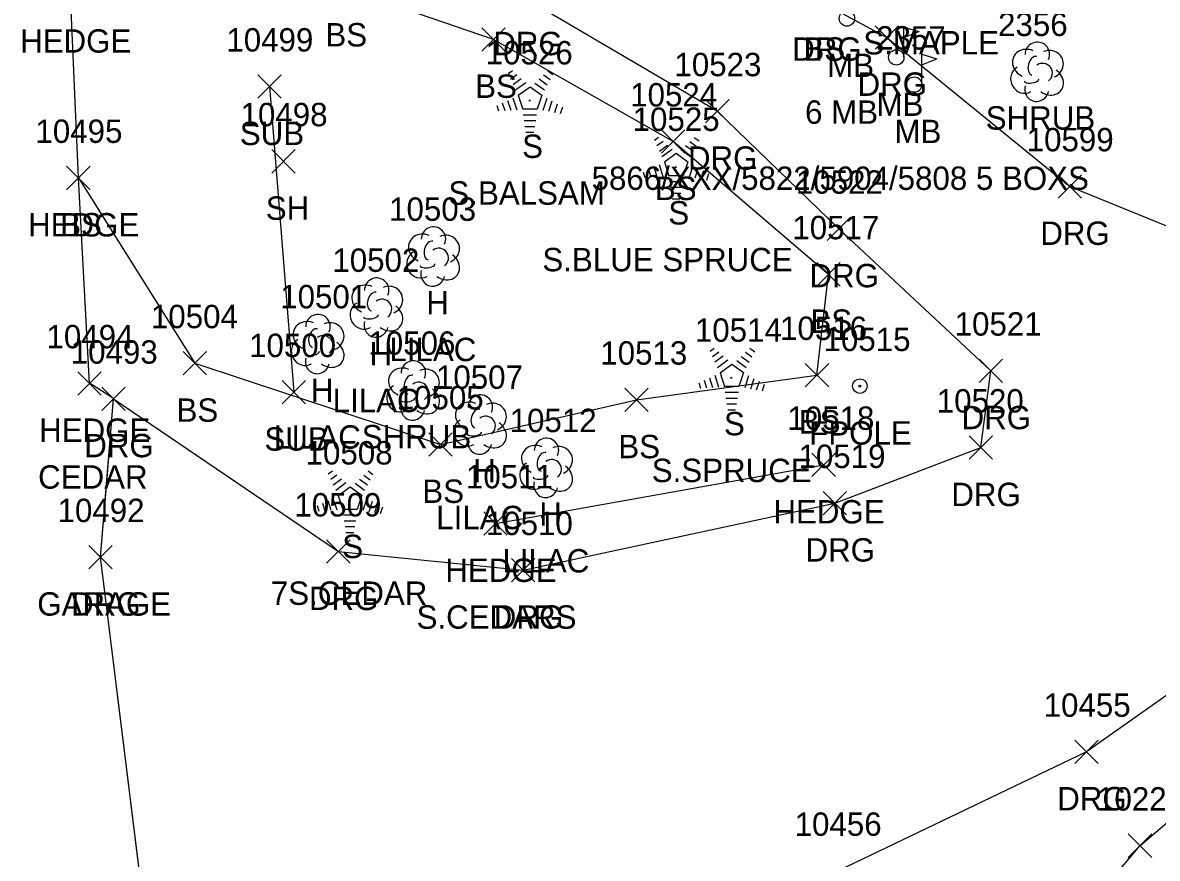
# Model space of a CAD drawing. Extents: x 1439173 to 1457902, y 641926 to 659889.
# Drawn here: x 1448003.1 to 1448100.1, y 647159.4 to 647230.9 of the extents above; entities that cross this region are included whole.
import ezdxf

# ---------------------------------------------------------------- set-up
doc = ezdxf.new("R2010")
doc.units = 0
for name, color, linetype in [('L_A', 7, 'Continuous'), ('L_C', 7, 'Continuous'), ('L_I', 7, 'Continuous'), ('L_TIC', 7, 'Continuous'), ('LAHR', 7, 'Continuous'), ('LBC', 7, 'Continuous'), ('LELB', 7, 'Continuous'), ('LFP', 7, 'Continuous'), ('LMB', 7, 'Continuous'), ('LSH', 7, 'Continuous'), ('LSOGP', 7, 'Continuous'), ('LTC', 7, 'Continuous'), ('LTD', 7, 'Continuous'), ('R_A', 7, 'Continuous'), ('R_I', 7, 'Continuous'), ('R_TIC', 7, 'Continuous'), ('RDG', 7, 'Continuous'), ('U_A', 7, 'Continuous'), ('U_I', 7, 'Continuous'), ('U_TIC', 7, 'Continuous'), ('UUU', 7, 'Continuous')]:
    doc.layers.add(name, color=color, linetype=linetype)

msp = doc.modelspace()

# ---------------------------------------------------------------- linework, layer by layer
at = {"layer": 'L_TIC'}
for points in [[(1448042.314, 647228.432), (1448044.314, 647230.432)], [(1448044.314, 647228.432), (1448042.314, 647230.432)], [(1448057.681, 647219.696), (1448059.681, 647221.696)], [(1448059.681, 647219.696), (1448057.681, 647221.696)], [(1448024.365, 647218.006), (1448026.365, 647220.006)], [(1448026.365, 647218.006), (1448024.365, 647220.006)], [(1448006.825, 647216.582), (1448008.825, 647218.582)], [(1448008.825, 647216.582), (1448006.825, 647218.582)], [(1448006.825, 647216.582), (1448008.825, 647218.582)], [(1448008.825, 647216.582), (1448006.825, 647218.582)], [(1448070.981, 647208.343), (1448072.981, 647210.343)], [(1448072.981, 647208.343), (1448070.981, 647210.343)], [(1448016.779, 647200.739), (1448018.779, 647202.739)], [(1448018.779, 647200.739), (1448016.779, 647202.739)], [(1448069.987, 647199.734), (1448071.987, 647201.734)], [(1448071.987, 647199.734), (1448069.987, 647201.734)], [(1448007.77, 647199.02), (1448009.77, 647201.02)], [(1448009.77, 647199.02), (1448007.77, 647201.02)], [(1448054.559, 647197.621), (1448056.559, 647199.621)], [(1448056.559, 647197.621), (1448054.559, 647199.621)], [(1448037.796, 647193.8), (1448039.796, 647195.8)], [(1448039.796, 647193.8), (1448037.796, 647195.8)], [(1448070.56, 647192.046), (1448072.56, 647194.046)], [(1448072.56, 647192.046), (1448070.56, 647194.046)], [(1448042.505, 647187.044), (1448044.505, 647189.044)], [(1448044.505, 647187.044), (1448042.505, 647189.044)], [(1448008.715, 647184.162), (1448010.715, 647186.162)], [(1448010.715, 647184.162), (1448008.715, 647186.162)], [(1448097.606, 647159.494), (1448099.606, 647161.494)], [(1448099.606, 647159.494), (1448097.606, 647161.494)]]:
    msp.add_lwpolyline(points, dxfattribs=at)
at = {"layer": 'LAHR'}
for points in [[(1448008.77, 647200.02), (1448007.825, 647217.582), (1448007.146, 647233.297)], [(1448043.505, 647188.044), (1448071.56, 647193.046)], [(1448080.435, 647069.069), (1448093.61, 647079.441), (1448095.055, 647091.51), (1448086.709, 647103.901), (1448078.141, 647117.067), (1448077.759, 647130.824), (1448085.363, 647144.088), (1448090.665, 647151.083), (1448098.606, 647160.494), (1448114.208, 647173.812)]]:
    msp.add_lwpolyline(points, dxfattribs=at)
at = {"layer": 'LBC'}
msp.add_lwpolyline([(1448014.179, 647149.261), (1448009.715, 647185.162)], dxfattribs=at)
at = {"layer": 'LELB'}
msp.add_lwpolyline([(1448007.825, 647217.582), (1448017.779, 647201.739), (1448038.796, 647194.8), (1448055.559, 647198.621), (1448070.987, 647200.734), (1448071.981, 647209.343), (1448058.681, 647220.696), (1448043.314, 647229.432), (1448030.507, 647233.829), (1448022.679, 647242.591)], dxfattribs=at)
at = {"layer": 'LFP'}
for radius in [0.625, 0.0833]:
    msp.add_circle((1448074.652, 647199.785), radius, dxfattribs=at)
at = {"layer": 'LMB'}
for p, q in [((1448078.418, 647230.491), (1448079.712, 647230.109)), ((1448078.424, 647227.899), (1448078.423, 647230.494)), ((1448078.423, 647229.592), (1448079.706, 647230.1)), ((1448077.768, 647227.891), (1448077.768, 647227.891)), ((1448079.954, 647228.163), (1448081.248, 647227.781)), ((1448079.96, 647225.571), (1448079.959, 647228.166)), ((1448079.959, 647227.264), (1448081.242, 647227.772)), ((1448079.304, 647225.563), (1448079.304, 647225.563))]:
    msp.add_line(p, q, dxfattribs=at)
for centre in [(1448073.55, 647231.217), (1448077.768, 647227.891), (1448079.304, 647225.563)]:
    msp.add_circle(centre, 0.656, dxfattribs=at)
at = {"layer": 'LSH'}
for p, q in [((1448089.785, 647226.719), (1448089.785, 647226.719)), ((1448089.785, 647226.719), (1448089.785, 647226.719)), ((1448036.43, 647199.464), (1448036.43, 647199.464)), ((1448036.43, 647199.464), (1448036.43, 647199.464))]:
    msp.add_line(p, q, dxfattribs=at)
for centre in [(1448089.831, 647228.153), (1448036.476, 647200.898)]:
    msp.add_arc(centre, 1.047, 335.52715, 180.95627, dxfattribs=at)
for centre, major_axis, ratio, start_param, end_param in [((1448088.993, 647227.385), (1.21, -0.512), 0.895232, 1.570796, 4.712389), ((1448089.576, 647227.177), (-0.208, -0.792), 0.645439, 3.141593, 6.283185), ((1448090.826, 647227.302), (-1.141, -0.483), 0.949671, 1.570796, 4.712389), ((1448088.702, 647226.01), (0.584, -1.042), 0.959034, 3.141593, 6.283185), ((1448090.285, 647226.552), (-0.5, 0.667), 0.989748, 3.141593, 6.283185), ((1448089.327, 647225.969), (-0.625, -0.083), 0.423636, 0, 3.141593), ((1448090.785, 647225.886), (-1.09, 0.792), 0.841452, 1.570796, 4.712389), ((1448089.785, 647225.219), (0.265, 1.061), 0.942809, 1.570796, 4.712389), ((1448035.638, 647200.131), (1.21, -0.512), 0.895232, 1.570796, 4.712389), ((1448036.221, 647199.923), (-0.208, -0.792), 0.645439, 3.141593, 6.283185), ((1448037.471, 647200.048), (-1.141, -0.483), 0.949671, 1.570796, 4.712389), ((1448035.347, 647198.756), (0.584, -1.042), 0.959034, 3.141593, 6.283185), ((1448036.93, 647199.298), (-0.5, 0.667), 0.989748, 3.141593, 6.283185), ((1448035.972, 647198.714), (-0.625, -0.083), 0.423636, 0, 3.141593), ((1448037.43, 647198.631), (-1.09, 0.792), 0.841452, 1.570796, 4.712389), ((1448036.43, 647197.964), (0.265, 1.061), 0.942809, 1.570796, 4.712389)]:
    msp.add_ellipse(centre, major_axis=major_axis, ratio=ratio, start_param=start_param, end_param=end_param, dxfattribs=at)
at = {"layer": 'LSOGP'}
msp.add_lwpolyline([(1448014.178, 647149.273), (1448009.714, 647185.174), (1448010.279, 647191.946), (1448010.844, 647198.718), (1448008.768, 647200.031), (1448007.825, 647217.593), (1448007.147, 647233.309), (1448010.527, 647240.895), (1448022.681, 647242.603), (1448028.133, 647243.372), (1448023.368, 647278.648), (1448017.454, 647321.225)], dxfattribs=at)
at = {"layer": 'LTC'}
for p, q in [((1448044.582, 647226.505), (1448044.936, 647226.763)), ((1448044.791, 647226.04), (1448045.321, 647226.424)), ((1448045.001, 647225.574), (1448045.705, 647226.085)), ((1448047.238, 647226.049), (1448047.917, 647225.555)), ((1448047.609, 647226.397), (1448048.158, 647225.998)), ((1448047.98, 647226.745), (1448048.399, 647226.441)), ((1448045.211, 647225.108), (1448046.089, 647225.746)), ((1448045.435, 647224.653), (1448046.447, 647225.388)), ((1448046.447, 647225.388), (1448047.444, 647224.663)), ((1448046.867, 647225.7), (1448047.676, 647225.112)), ((1448044.07, 647224.001), (1448044.281, 647223.349)), ((1448044.525, 647224.218), (1448044.796, 647223.382)), ((1448044.981, 647224.434), (1448045.311, 647223.415)), ((1448045.435, 647224.653), (1448045.822, 647223.46)), ((1448047.444, 647224.663), (1448047.053, 647223.46)), ((1448047.881, 647224.392), (1448047.543, 647223.352)), ((1448048.326, 647224.141), (1448048.038, 647223.257)), ((1448043.614, 647223.784), (1448043.766, 647223.316)), ((1448047.053, 647223.46), (1448045.822, 647223.46)), ((1448048.771, 647223.891), (1448048.533, 647223.162)), ((1448049.215, 647223.641), (1448049.028, 647223.067)), ((1448047.014, 647222.96), (1448045.87, 647222.96)), ((1448046.931, 647222.46), (1448045.942, 647222.46)), ((1448046.847, 647221.96), (1448046.015, 647221.96)), ((1448046.763, 647221.46), (1448046.088, 647221.46)), ((1448057.086, 647220.813), (1448057.441, 647221.07)), ((1448057.296, 647220.347), (1448057.825, 647220.732)), ((1448057.506, 647219.882), (1448058.209, 647220.393)), ((1448059.743, 647220.357), (1448060.422, 647219.863)), ((1448060.113, 647220.705), (1448060.663, 647220.306)), ((1448060.485, 647221.053), (1448060.904, 647220.749)), ((1448057.715, 647219.416), (1448058.593, 647220.054)), ((1448057.94, 647218.961), (1448058.951, 647219.695)), ((1448058.951, 647219.695), (1448059.948, 647218.97)), ((1448059.371, 647220.008), (1448060.181, 647219.419)), ((1448056.574, 647218.309), (1448056.786, 647217.657)), ((1448057.03, 647218.525), (1448057.301, 647217.69)), ((1448057.485, 647218.742), (1448057.816, 647217.722)), ((1448057.94, 647218.961), (1448058.327, 647217.767)), ((1448059.948, 647218.97), (1448059.557, 647217.767)), ((1448060.386, 647218.699), (1448060.048, 647217.66)), ((1448060.831, 647218.449), (1448060.543, 647217.564)), ((1448061.275, 647218.199), (1448061.038, 647217.469)), ((1448056.119, 647218.092), (1448056.271, 647217.624)), ((1448059.557, 647217.767), (1448058.327, 647217.767)), ((1448059.519, 647217.267), (1448058.374, 647217.267)), ((1448061.719, 647217.949), (1448061.533, 647217.374)), ((1448059.435, 647216.767), (1448058.447, 647216.767)), ((1448059.351, 647216.267), (1448058.52, 647216.267)), ((1448059.268, 647215.767), (1448058.593, 647215.767)), ((1448061.843, 647202.787), (1448062.197, 647203.044)), ((1448062.052, 647202.321), (1448062.581, 647202.705)), ((1448064.87, 647202.679), (1448065.419, 647202.279)), ((1448065.241, 647203.027), (1448065.66, 647202.722)), ((1448062.262, 647201.855), (1448062.965, 647202.367)), ((1448062.471, 647201.389), (1448063.35, 647202.027)), ((1448062.696, 647200.934), (1448063.708, 647201.669)), ((1448063.708, 647201.669), (1448064.705, 647200.944)), ((1448064.128, 647201.982), (1448064.937, 647201.393)), ((1448064.499, 647202.33), (1448065.178, 647201.837)), ((1448062.241, 647200.715), (1448062.572, 647199.696)), ((1448062.696, 647200.934), (1448063.083, 647199.741)), ((1448064.705, 647200.944), (1448064.313, 647199.741)), ((1448060.875, 647200.066), (1448061.027, 647199.598)), ((1448061.33, 647200.282), (1448061.542, 647199.631)), ((1448061.786, 647200.499), (1448062.057, 647199.664)), ((1448064.313, 647199.741), (1448063.083, 647199.741)), ((1448065.142, 647200.673), (1448064.804, 647199.634)), ((1448065.587, 647200.423), (1448065.299, 647199.538)), ((1448066.031, 647200.173), (1448065.794, 647199.443)), ((1448066.475, 647199.922), (1448066.289, 647199.348)), ((1448064.275, 647199.241), (1448063.13, 647199.241)), ((1448064.191, 647198.741), (1448063.203, 647198.741)), ((1448064.108, 647198.241), (1448063.276, 647198.241)), ((1448064.024, 647197.741), (1448063.349, 647197.741)), ((1448029.201, 647192.292), (1448029.556, 647192.55)), ((1448029.411, 647191.827), (1448029.94, 647192.211)), ((1448032.228, 647192.184), (1448032.778, 647191.785)), ((1448032.6, 647192.533), (1448033.019, 647192.228)), ((1448029.62, 647191.361), (1448030.324, 647191.872)), ((1448029.83, 647190.895), (1448030.708, 647191.533)), ((1448030.055, 647190.44), (1448031.066, 647191.175)), ((1448031.066, 647191.175), (1448032.063, 647190.45)), ((1448031.486, 647191.488), (1448032.296, 647190.899)), ((1448031.858, 647191.836), (1448032.537, 647191.342)), ((1448029.6, 647190.221), (1448029.931, 647189.202)), ((1448030.055, 647190.44), (1448030.442, 647189.247)), ((1448032.063, 647190.45), (1448031.672, 647189.247)), ((1448032.501, 647190.179), (1448032.163, 647189.139)), ((1448028.234, 647189.571), (1448028.386, 647189.104)), ((1448028.689, 647189.788), (1448028.901, 647189.136)), ((1448029.145, 647190.005), (1448029.416, 647189.169)), ((1448031.672, 647189.247), (1448030.442, 647189.247)), ((1448032.945, 647189.929), (1448032.658, 647189.044)), ((1448033.39, 647189.679), (1448033.153, 647188.949)), ((1448033.834, 647189.428), (1448033.648, 647188.854)), ((1448031.634, 647188.747), (1448030.489, 647188.747)), ((1448031.55, 647188.247), (1448030.562, 647188.247)), ((1448031.466, 647187.747), (1448030.635, 647187.747)), ((1448031.383, 647187.247), (1448030.708, 647187.247))]:
    msp.add_line(p, q, dxfattribs=at)
at = {"layer": 'LTD'}
for p, q in [((1448038.146, 647210.922), (1448038.146, 647210.922)), ((1448038.146, 647210.922), (1448038.146, 647210.922)), ((1448033.295, 647206.556), (1448033.295, 647206.556)), ((1448033.295, 647206.556), (1448033.295, 647206.556)), ((1448028.271, 647203.437), (1448028.271, 647203.437)), ((1448028.271, 647203.437), (1448028.271, 647203.437)), ((1448042.155, 647196.555), (1448042.155, 647196.555)), ((1448042.155, 647196.555), (1448042.155, 647196.555)), ((1448047.809, 647192.853), (1448047.809, 647192.853)), ((1448047.809, 647192.853), (1448047.809, 647192.853))]:
    msp.add_line(p, q, dxfattribs=at)
for centre in [(1448038.193, 647212.355), (1448033.342, 647207.99), (1448028.317, 647204.87), (1448042.202, 647197.989), (1448047.855, 647194.287)]:
    msp.add_arc(centre, 1.047, 335.52715, 180.95627, dxfattribs=at)
for centre, major_axis, ratio, start_param, end_param in [((1448037.354, 647211.588), (1.21, -0.512), 0.895232, 1.570796, 4.712389), ((1448039.188, 647211.505), (-1.141, -0.483), 0.949671, 1.570796, 4.712389), ((1448037.938, 647211.38), (-0.208, -0.792), 0.645439, 3.141593, 6.283185), ((1448038.646, 647210.755), (-0.5, 0.667), 0.989748, 3.141593, 6.283185), ((1448037.063, 647210.213), (0.584, -1.042), 0.959034, 3.141593, 6.283185), ((1448039.146, 647210.088), (-1.09, 0.792), 0.841452, 1.570796, 4.712389), ((1448038.146, 647209.422), (0.265, 1.061), 0.942809, 1.570796, 4.712389), ((1448037.688, 647210.171), (-0.625, -0.083), 0.423636, 0, 3.141593), ((1448032.503, 647207.222), (1.21, -0.512), 0.895232, 1.570796, 4.712389), ((1448034.336, 647207.139), (-1.141, -0.483), 0.949671, 1.570796, 4.712389), ((1448033.087, 647207.014), (-0.208, -0.792), 0.645439, 3.141593, 6.283185), ((1448032.212, 647205.847), (0.584, -1.042), 0.959034, 3.141593, 6.283185), ((1448033.795, 647206.389), (-0.5, 0.667), 0.989748, 3.141593, 6.283185), ((1448034.295, 647205.722), (-1.09, 0.792), 0.841452, 1.570796, 4.712389), ((1448032.837, 647205.806), (-0.625, -0.083), 0.423636, 0, 3.141593), ((1448027.479, 647204.103), (1.21, -0.512), 0.895232, 1.570796, 4.712389), ((1448028.062, 647203.895), (-0.208, -0.792), 0.645439, 3.141593, 6.283185), ((1448029.312, 647204.02), (-1.141, -0.483), 0.949671, 1.570796, 4.712389), ((1448033.295, 647205.056), (0.265, 1.061), 0.942809, 1.570796, 4.712389), ((1448027.187, 647202.728), (0.584, -1.042), 0.959034, 3.141593, 6.283185), ((1448028.771, 647203.27), (-0.5, 0.667), 0.989748, 3.141593, 6.283185), ((1448027.812, 647202.686), (-0.625, -0.083), 0.423636, 0, 3.141593), ((1448029.271, 647202.603), (-1.09, 0.792), 0.841452, 1.570796, 4.712389), ((1448028.271, 647201.937), (0.265, 1.061), 0.942809, 1.570796, 4.712389), ((1448041.363, 647197.222), (1.21, -0.512), 0.895232, 1.570796, 4.712389), ((1448041.947, 647197.014), (-0.208, -0.792), 0.645439, 3.141593, 6.283185), ((1448043.197, 647197.139), (-1.141, -0.483), 0.949671, 1.570796, 4.712389), ((1448041.072, 647195.847), (0.584, -1.042), 0.959034, 3.141593, 6.283185), ((1448042.655, 647196.389), (-0.5, 0.667), 0.989748, 3.141593, 6.283185), ((1448041.697, 647195.805), (-0.625, -0.083), 0.423636, 0, 3.141593), ((1448043.155, 647195.722), (-1.09, 0.792), 0.841452, 1.570796, 4.712389), ((1448042.155, 647195.055), (0.265, 1.061), 0.942809, 1.570796, 4.712389), ((1448047.017, 647193.52), (1.21, -0.512), 0.895232, 1.570796, 4.712389), ((1448047.6, 647193.311), (-0.208, -0.792), 0.645439, 3.141593, 6.283185), ((1448048.85, 647193.437), (-1.141, -0.483), 0.949671, 1.570796, 4.712389), ((1448046.725, 647192.145), (0.584, -1.042), 0.959034, 3.141593, 6.283185), ((1448048.309, 647192.686), (-0.5, 0.667), 0.989748, 3.141593, 6.283185), ((1448048.809, 647192.02), (-1.09, 0.792), 0.841452, 1.570796, 4.712389), ((1448047.35, 647192.103), (-0.625, -0.083), 0.423636, 0, 3.141593), ((1448047.809, 647191.353), (0.265, 1.061), 0.942809, 1.570796, 4.712389)]:
    msp.add_ellipse(centre, major_axis=major_axis, ratio=ratio, start_param=start_param, end_param=end_param, dxfattribs=at)
at = {"layer": 'R_TIC'}
for points in [[(1448075.967, 647228.606), (1448077.967, 647230.606)], [(1448077.967, 647228.606), (1448075.967, 647230.606)], [(1448061.464, 647222.285), (1448063.464, 647224.285)], [(1448063.464, 647222.285), (1448061.464, 647224.285)], [(1448091.597, 647215.862), (1448093.597, 647217.862)], [(1448093.597, 647215.862), (1448091.597, 647217.862)], [(1448071.853, 647212.238), (1448073.853, 647214.238)], [(1448073.853, 647212.238), (1448071.853, 647214.238)], [(1448084.863, 647200.104), (1448086.863, 647202.104)], [(1448086.863, 647200.104), (1448084.863, 647202.104)], [(1448009.842, 647197.705), (1448011.842, 647199.705)], [(1448011.842, 647197.705), (1448009.842, 647199.705)], [(1448083.986, 647193.529), (1448085.986, 647195.529)], [(1448085.986, 647193.529), (1448083.986, 647195.529)], [(1448071.517, 647188.786), (1448073.517, 647190.786)], [(1448073.517, 647188.786), (1448071.517, 647190.786)], [(1448008.715, 647184.162), (1448010.715, 647186.162)], [(1448010.715, 647184.162), (1448008.715, 647186.162)], [(1448029.057, 647184.639), (1448031.057, 647186.639)], [(1448031.057, 647184.639), (1448029.057, 647186.639)], [(1448044.859, 647183.051), (1448046.859, 647185.051)], [(1448046.859, 647183.051), (1448044.859, 647185.051)], [(1448093.039, 647167.513), (1448095.039, 647169.513)], [(1448095.039, 647167.513), (1448093.039, 647169.513)]]:
    msp.add_lwpolyline(points, dxfattribs=at)
at = {"layer": 'RDG'}
for points in [[(1448009.715, 647185.162), (1448010.842, 647198.705), (1448030.057, 647185.639), (1448045.859, 647184.051), (1448072.517, 647189.786), (1448084.986, 647194.529), (1448085.863, 647201.104), (1448072.853, 647213.238), (1448062.464, 647223.285), (1448045.821, 647233.079), (1448034.3, 647243.69), (1448029.487, 647276.287), (1448023.129, 647322.601), (1448031.461, 647337.648), (1448032.306, 647341.805), (1448037.817, 647358.729), (1448043.207, 647370.792), (1448039.453, 647382.387)], [(1448066.291, 647375.336), (1448057.69, 647354.331), (1448048.349, 647327.308), (1448044.921, 647307.56), (1448045.771, 647281.961), (1448051.012, 647260.428), (1448059.311, 647244.506), (1448071.381, 647232.608), (1448076.967, 647229.606), (1448092.597, 647216.862), (1448110.057, 647209.764), (1448120.765, 647212.608), (1448129.311, 647223.42), (1448133.303, 647233.022), (1448137.141, 647239.411)], [(1448145.856, 647185.047), (1448142.514, 647186.875), (1448130.402, 647190.219), (1448114.153, 647182.72), (1448094.039, 647168.513), (1448072.801, 647158.336), (1448057.442, 647150.983), (1448052.623, 647150.109), (1448043.749, 647148.801), (1448040.446, 647147.96), (1448029.027, 647147.098), (1448022.467, 647146.77), (1448014.179, 647149.261)]]:
    msp.add_lwpolyline(points, dxfattribs=at)
at = {"layer": 'U_TIC'}
for points in [[(1448023.161, 647224.395), (1448025.161, 647226.395)], [(1448025.161, 647224.395), (1448023.161, 647226.395)], [(1448025.262, 647198.271), (1448027.262, 647200.271)], [(1448027.262, 647198.271), (1448025.262, 647200.271)]]:
    msp.add_lwpolyline(points, dxfattribs=at)
at = {"layer": 'UUU'}
msp.add_lwpolyline([(1448024.161, 647225.395), (1448026.262, 647199.271)], dxfattribs=at)

# ---------------------------------------------------------------- texts
at = {"layer": 'L_A'}
for s, p in [('BS', (1448028.948, 647228.829)), ('HEDGE', (1448002.847, 647228.297)), ('BS', (1448069.822, 647227.608)), ('MB', (1448071.857, 647226.217)), ('BS', (1448041.755, 647224.432)), ('MB', (1448076.075, 647222.891)), ('SHRUB', (1448085.415, 647221.719)), ('MB', (1448077.611, 647220.563)), ('S', (1448045.772, 647219.297)), ('BS', (1448057.122, 647215.696)), ('SH', (1448023.853, 647214.006)), ('S', (1448058.277, 647213.605)), ('HEDGE', (1448003.526, 647212.582)), ('BS', (1448006.266, 647212.582)), ('H', (1448037.579, 647205.922)), ('BS', (1448070.422, 647204.343)), ('H', (1448032.728, 647201.556)), ('H', (1448027.704, 647198.437)), ('BS', (1448016.22, 647196.739)), ('HEDGE', (1448004.471, 647195.02)), ('S', (1448063.033, 647195.578)), ('BS', (1448069.428, 647195.734)), ('FPOLE', (1448070.321, 647194.785)), ('SHRUB', (1448032.06, 647194.464)), ('BS', (1448054, 647193.621)), ('H', (1448041.588, 647191.555)), ('BS', (1448037.237, 647189.8)), ('HEDGE', (1448067.26, 647188.046)), ('H', (1448047.242, 647187.853)), ('S', (1448030.392, 647185.084)), ('HEDGE', (1448039.206, 647183.044)), ('GARAGE', (1448004.313, 647180.162))]:
    msp.add_text(s, height=2, dxfattribs=at).set_placement(p)
at = {"layer": 'L_C'}
for s, p in [('S.MAPLE', (1448074.949, 647228.145)), ('6 MB', (1448069.967, 647222.217)), ('5866/XXX/5822/5904/5808 5 BOXS', (1448051.713, 647216.563)), ('S.BALSAM', (1448039.473, 647215.297)), ('S.BLUE SPRUCE', (1448047.505, 647209.605)), ('LILAC', (1448034.422, 647201.922)), ('LILAC', (1448029.571, 647197.556)), ('LILAC', (1448024.546, 647194.437)), ('CEDAR', (1448004.384, 647191.02)), ('S.SPRUCE', (1448056.86, 647191.578)), ('LILAC', (1448038.431, 647187.555)), ('LILAC', (1448044.084, 647183.853)), ('7S.CEDAR', (1448024.29, 647181.084)), ('S.CEDARS', (1448036.749, 647179.044))]:
    msp.add_text(s, height=2, dxfattribs=at).set_placement(p)
at = {"layer": 'L_I'}
for s, p in [('2356', (1448086.47, 647229.719)), ('2357', (1448076.044, 647228.563)), ('10526', (1448042.662, 647227.297)), ('10524', (1448055.012, 647223.696)), ('10498', (1448021.696, 647222.006)), ('10525', (1448055.222, 647221.605)), ('10495', (1448004.156, 647220.582)), ('10495', (1448004.156, 647220.582)), ('10503', (1448034.398, 647213.922)), ('10517', (1448068.879, 647212.343)), ('10502', (1448029.547, 647209.556)), ('10501', (1448025.089, 647206.437)), ('10504', (1448014.031, 647204.739)), ('10514', (1448060.545, 647203.578)), ('10516', (1448067.829, 647203.734)), ('10494', (1448005.1, 647203.02)), ('10515', (1448071.55, 647202.785)), ('10506', (1448032.627, 647202.464)), ('10513', (1448052.456, 647201.621)), ('10507', (1448038.407, 647199.555)), ('10505', (1448035.048, 647197.8)), ('10512', (1448044.706, 647195.853)), ('10518', (1448068.457, 647196.046)), ('10508', (1448027.258, 647193.084)), ('10511', (1448040.97, 647191.044)), ('10492', (1448006.046, 647188.162)), ('10222', (1448094.937, 647163.494))]:
    msp.add_text(s, height=2, dxfattribs=at).set_placement(p)
at = {"layer": 'LTC'}
for p in [(1448046.329, 647224.401), (1448058.834, 647218.709), (1448063.59, 647200.682), (1448030.949, 647190.188)]:
    msp.add_text('.', height=1.037, rotation=270, dxfattribs=at).set_placement(p)
at = {"layer": 'R_A'}
for p in [(1448043.309, 647228.079), (1448068.869, 647227.608), (1448074.455, 647224.606), (1448059.953, 647218.285), (1448090.085, 647211.862), (1448070.341, 647208.238), (1448083.351, 647196.104), (1448008.33, 647193.705), (1448082.475, 647189.529), (1448070.005, 647184.786), (1448027.545, 647180.639), (1448007.203, 647180.162), (1448043.347, 647179.051), (1448091.528, 647163.513)]:
    msp.add_text('DRG', height=2, dxfattribs=at).set_placement(p)
at = {"layer": 'R_I'}
for s, p in [('10523', (1448058.795, 647226.285)), ('10599', (1448088.92, 647219.862)), ('10522', (1448069.183, 647216.238)), ('10521', (1448082.76, 647204.104)), ('10493', (1448007.173, 647201.705)), ('10520', (1448081.23, 647197.529)), ('10519', (1448069.407, 647192.786)), ('10492', (1448006.046, 647188.162)), ('10509', (1448026.301, 647188.639)), ('10510', (1448042.67, 647187.051)), ('10455', (1448090.37, 647171.513)), ('10456', (1448069.077, 647161.336))]:
    msp.add_text(s, height=2, dxfattribs=at).set_placement(p)
at = {"layer": 'U_A'}
for p in [(1448021.633, 647220.395), (1448023.735, 647194.271)]:
    msp.add_text('SUB', height=2, dxfattribs=at).set_placement(p)
at = {"layer": 'U_I'}
for s, p in [('10499', (1448020.483, 647228.395)), ('10500', (1448022.428, 647202.271))]:
    msp.add_text(s, height=2, dxfattribs=at).set_placement(p)

doc.saveas('drawing.dxf')
